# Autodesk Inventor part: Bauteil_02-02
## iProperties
Created: 2007-04
Part Number: Bauteil_02-02
Document SubType Name: Modeling
Designer: Sascha Fleischer
Author: Sascha Fleischer
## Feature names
1. Abgeleiteter Körper1 [Tagging]
